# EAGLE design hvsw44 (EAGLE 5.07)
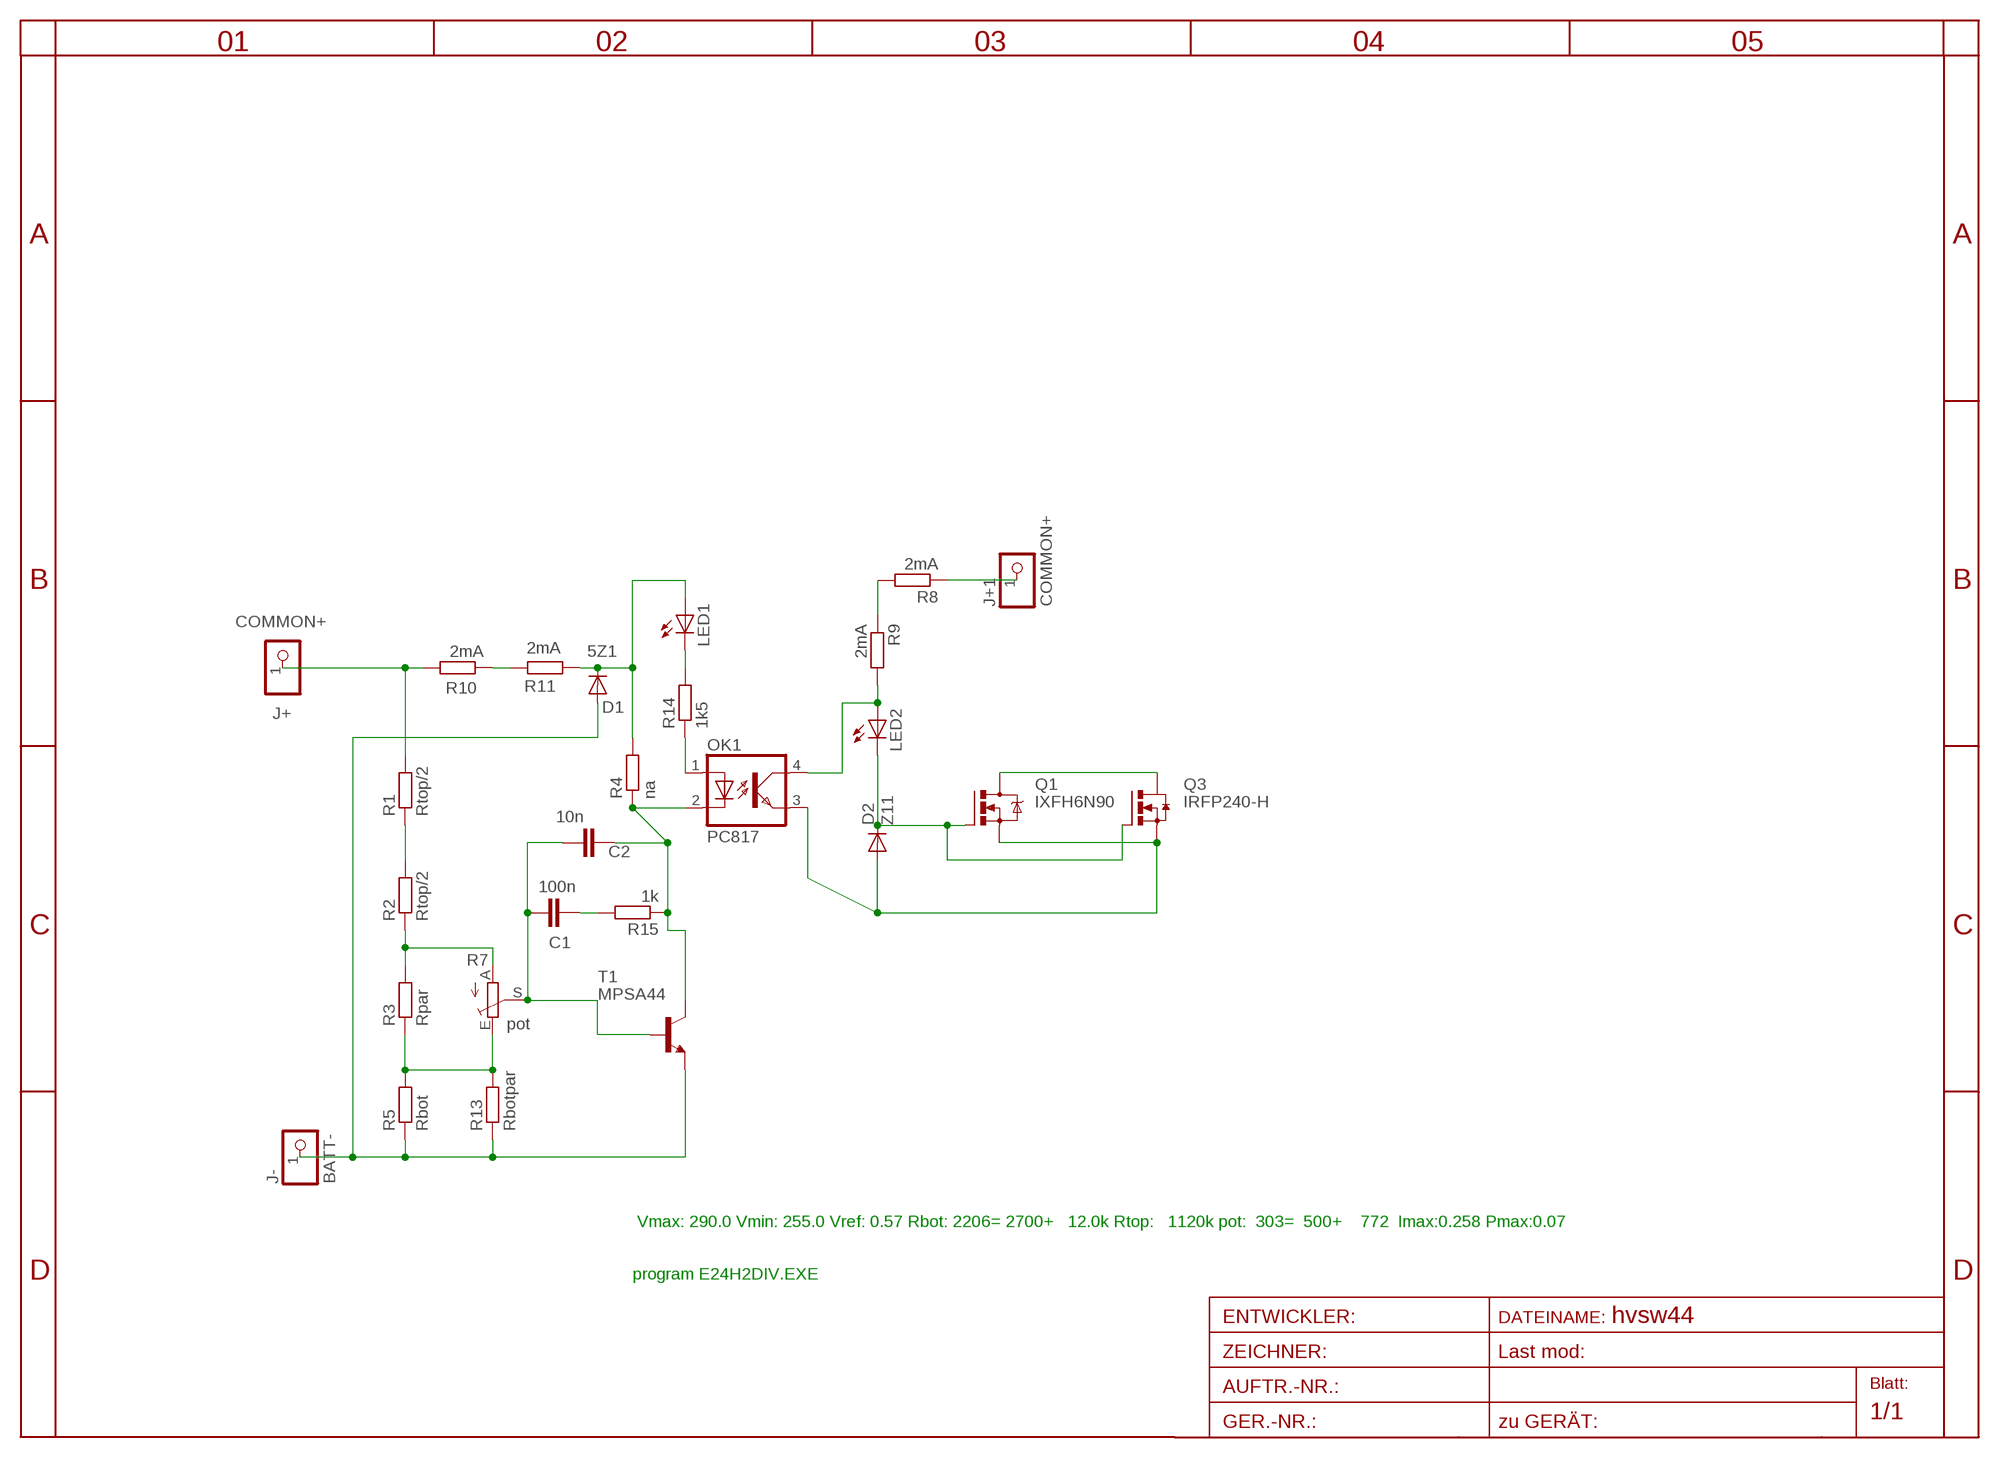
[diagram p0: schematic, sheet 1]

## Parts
C1  100n  C-EUC0805  [C0805]
C2  10n  C-EUC0805  [C0805]
D1  5Z1  DIODE-MINIMELF  [MINIMELF]
D2  Z11  DIODE-MINIMELF  [MINIMELF]
J+  COMMON+  PINHD-1X11X0.4  [1X01]
J+1  COMMON+  PINHD-1X11X0.4  [1X01]
J-  BATT-  PINHD-1X11X0.4  [1X01]
LED1  LED3MM  [LED3MM]
LED2  LED3MM  [LED3MM]
OK1  PC817  [DIL04]
Q1  IXFH6N90  [TO-247AD-V]
Q3  IRFP240-H  [TO247BH]
R1  Rtop/2  R-EU_R1206  [R1206]
R2  Rtop/2  R-EU_R1206  [R1206]
R3  Rpar  R-EU_R1206  [R1206]
R4  na  R-EU_R0805  [R0805]
R5  Rbot  R-EU_R0805  [R0805]
R7  pot  TRIM_EU-CA6V  [CA6V]
R8  2mA  R-EU_R1206  [R1206]
R9  2mA  R-EU_R1206  [R1206]
R10  2mA  R-EU_R1206  [R1206]
R11  2mA  R-EU_R1206  [R1206]
R13  Rbotpar  R-EU_R0805  [R0805]
R14  1k5  R-EU_R0805  [R0805]
R15  1k  R-EU_R0805  [R0805]
T1  MPSA44  BC338-40-NPN-TO92-EBC  [TO92-EBC]

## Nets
A: R2.1 R3.2 R7.A
BATT-: D1.A J-.1 R5.1 R13.1 T1.E
D: Q1.D Q3.D
E: R3.1 R5.2 R7.E R13.2
G: D2.C LED2.K(C) Q1.G Q3.G
N$2: C1.2 C2.2 R7.S T1.B
N$3: C1.1 R15.2
N$5: J+.1 R1.2 R10.2
N$6: J+1.1 R8.1
N$7: OK1.1(A) R14.1
N$8: LED2.A OK1.4(COL) R9.2
N$10: LED1.K(C) R14.2
N$12: R8.2 R9.1
N$15: R1.1 R2.2
N$16: R10.1 R11.2
OK2: C2.1 OK1.2(C) R4.1 R15.1 T1.C
S: D2.A OK1.3(EMIT) Q1.S Q3.S
V_R: D1.C LED1.A R4.2 R11.1

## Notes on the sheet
- Vmax: 290.0 Vmin: 255.0 Vref: 0.57 Rbot: 2206= 2700+   12.0k Rtop:   1120k pot:  303=  500+    772  Imax:0.258 Pmax:0.07
- program E24H2DIV.EXE

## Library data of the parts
C1 C2 = rcl:C-EU: CAPACITOR, European symbol
D1 D2 = diode:DIODE-: DIODE
J+ J+1 J- = pinhead:PINHD-1X1: PIN HEADER
LED1 LED2 = led:LED: LED
OK1 = optocoupler:PC817: SHARP OPTO COUPLER
Q1 = transistor-power:IXF?6N*: HiPerFET (TM) Power MOSFET N-Channel Enhancement Mode HDMOS Family Source: http://www.ixys.com/91529.pdf
Q3 = transistor-power:IRFP240: HEXFET Power MosFet Source: http://www.irf.com/
R1-R5 R8-R11 R13-R15 = rcl:R-EU_: RESISTOR, European symbol
R7 = pot:TRIM_EU-: POTENTIOMETER
T1 = transistor:*-NPN-: NPN Transistror BF959 corrected 2008.03.06

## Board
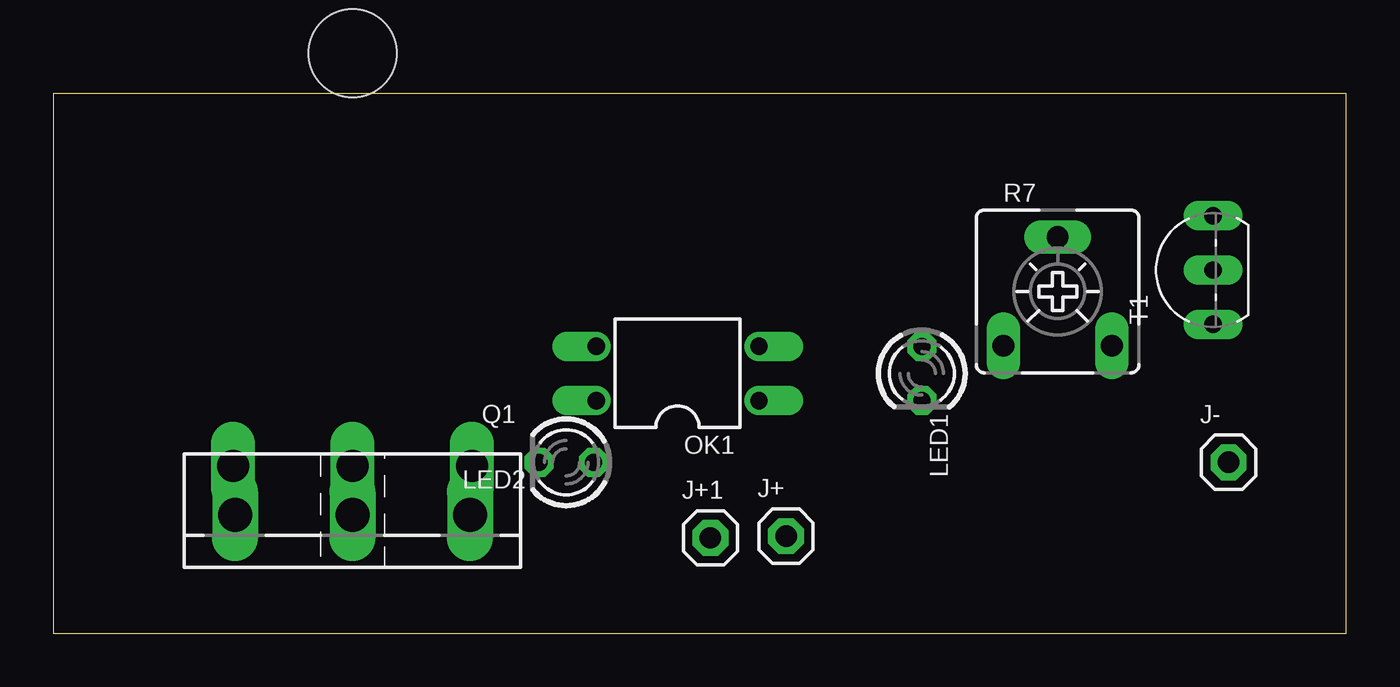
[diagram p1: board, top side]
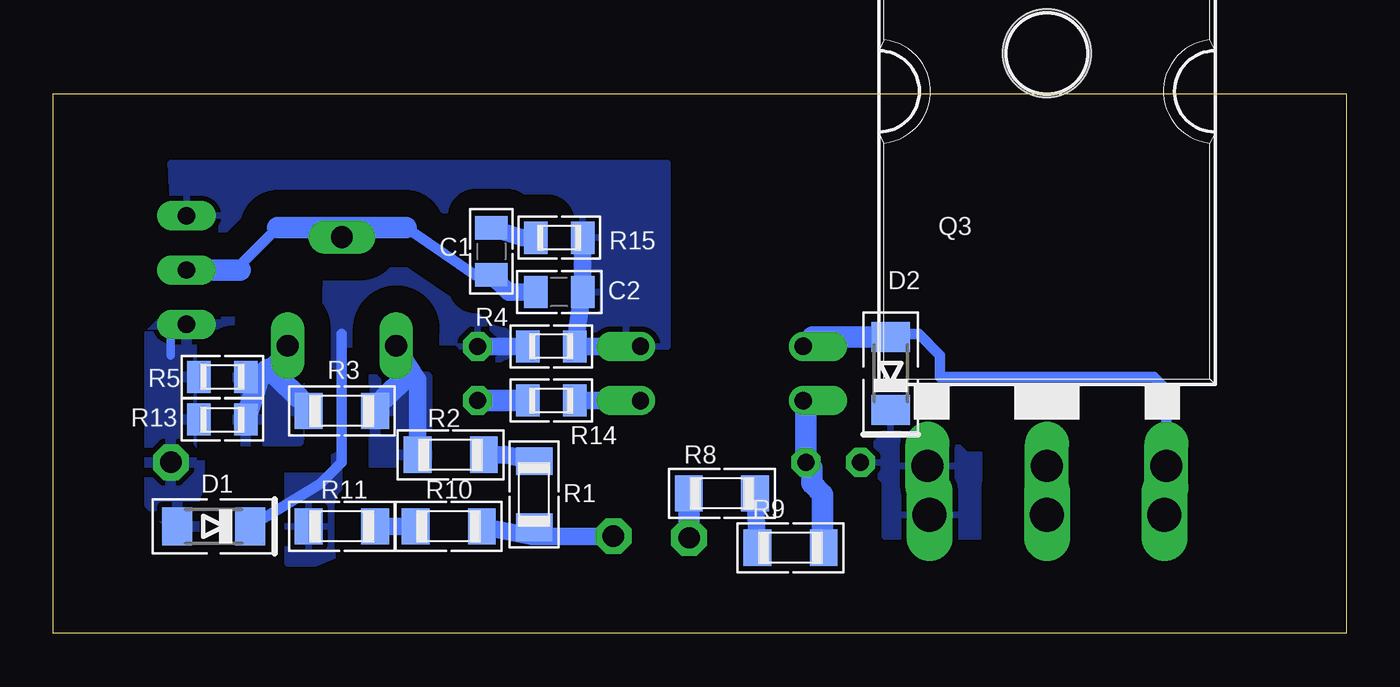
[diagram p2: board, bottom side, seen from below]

Size 60.5 x 25.26 mm. Coordinates in mm from the lower left corner, seen from the top.
Outline: 0,0 60.5,0 60.5,25.26 0,25.26 0,0
Copper layers (1*16): Top 0.035mm / dielectric 1.5mm / Bottom 0.035mm
Design rules "default *": minimum track width 10mil, minimum drill 20mil, track to track 8mil, track to pad 8mil, pad to pad 8mil, via to via 8mil, smd to smd 8mil, copper to edge 3mm, drill to drill 8mil, minimum pad ring 11mil, minimum via ring 8mil, stop-mask expansion 4mil, vias tented up to drill 0mil, thermal gap 10mil

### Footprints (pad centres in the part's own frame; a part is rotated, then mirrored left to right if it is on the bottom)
C0805 = smd 1.1 x 1.5: 1 -1.1,0; 2 1.1,0
MINIMELF = smd 1.4 x 1.8: A 1.7,0; C -1.7,0
1X01 = drill 1 pad 1.676 octagon: 1 0,0
LED3MM = drill 0.8 pad 1.27 octagon: A -1.27,0; K 1.27,0
DIL04 = drill 0.813 offset: 1 -1.27,-3.81; 2 1.27,-3.81; 3 1.27,3.81; 4 -1.27,3.81
TO-247AD-V = drill 1.6 long: D 0,-2.54; G -5.5,-2.54; S 5.5,-2.54
TO247BH = drill 1.499 long: D 0,-10.16; G -5.588,-10.16; S 5.588,-10.16 | hole 4.115: 0,9.144
R1206 = smd 1.3 x 1.7: 1 -1.55,0; 2 1.55,0
R0805 = smd 1.1 x 1.5: 1 -1.1,0; 2 1.1,0
CA6V = drill 1.016 long: A -2.54,-2.54; E 2.54,-2.54; S 0,2.54
TO92-EBC = drill 0.813 long: B 0,-1.27; C 2.54,-1.27; E -2.54,-1.27

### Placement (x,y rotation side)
C1  40.01,17.88 270 bottom
C2  36.83,15.97 180 bottom
D1  53,5 180 bottom
D2  21.32,12.16 90 bottom
J+  34.29,4.54 0 top
J+1  30.75,4.46 0 top
J-  55,8 0 top
LED1  40.64,12.16 270 top
LED2  24,8 180 top
OK1  29.21,12.16 90 top
Q1  14,3 180 top
Q3  14,18 0 bottom
R1  38,6.5 270 bottom
R2  41.91,8.35 0 bottom
R3  47,10.4 0 bottom
R4  37.2,13.43 180 bottom
R5  52.6,12 0 bottom
R7  47,16 0 top
R8  29.21,6.54 0 bottom
R9  26,4 0 bottom
R10  42,5 0 bottom
R11  47,5 0 bottom
R13  52.6,10 0 bottom
R14  37.2,10.89 180 bottom
R15  36.83,18.51 180 bottom
T1  53,17 90 top

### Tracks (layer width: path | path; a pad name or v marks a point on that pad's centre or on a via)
A
  Bottom 0.5: 45,11 R3.2 | 44,12 44,13 R7.A
  Bottom 0.813: R2.1 43.46,11.88 R7.A
  Bottom 1: 44,12 45,11
  pour Bottom (isolate 1): 43,12 46,12 46,8 43,8
BATT-
  Bottom 0.406: T1.E 55,14.46 55,13
  pour Bottom (isolate 1.676, rank 3): 52,15 55,15 56,14 56,6 54,4 51,4 51,14
D
  Bottom 0.5: Q1.D Q3.D
E
  Bottom 0.5: 49,11 R3.1 | 50,12 50,13 R7.E
  Bottom 0.813: R5.2 50.47,12.35 49.36,13.26 R7.E
  Bottom 1: 50,12 49,11 | R13.2 50.9,11.92 50.47,12.35
  pour Bottom (isolate 1): 49,12 52,12 52,9 49,9
G
  Bottom 0.813: D2.C 21.16,10.46
  pour Bottom (isolate 2): 16.43,8.35 17.78,8.35 20.32,10.89 25.4,10.89 25.4,9.62 24.13,9.62 21.59,7.08 21.59,4.54 16.43,4.54
N$2
  Bottom 0.406: 51.76,17.24 51.76,17
  Bottom 0.5: C1.2 40.77,16.77 44,19 | 50,19 51.76,17.24 | 47.46,19 R7.S
  Bottom 0.813: C2.2 39.2,15.97 C1.2
  Bottom 1: 44,19 47.46,19 50,19 | 51.76,17 T1.B
N$3
  Bottom 0.813: R15.2 38.56,18.51 C1.1
N$5
  Bottom 0.813: J+.1 38.1,4.54 | 38.1,4.54 R10.2 | 38.1,4.54 R1.2
N$6
  Bottom 1: J+1.1 R8.1
N$7
  Bottom 0.813: OK1.1 R14.1
N$8
  Bottom 1: R9.2 24.5,4 24.5,6.5 25,7 25,7.73 LED2.A 25.27,10.76 OK1.4
N$10
  Bottom 1: R14.2 LED1.K
N$12
  Bottom 0.813: R9.1 R8.2
N$15
  Bottom 0.813: R1.1 39.38,8.36 39.37,8.35 R2.2
N$16
  Bottom 0.813: R10.1 R11.2
OK2
  Bottom 0.813: OK1.2 R4.1 C2.1 R15.1
  pour Bottom (isolate 1.27): 31.75,13.43 31.75,22 55,22 54.8,18.51 36.83,18.51 36.83,13.43
S
  Bottom 0.5: Q3.S 8.41,11.41 9,12 19,12 19,13 20,14 21.46,14 | 21.46,14 22,14 | 21.46,14 D2.A | 24.97,13.86 OK1.3
  Bottom 1: D2.A 24.97,13.86 | Q1.S 8.5,7.75 Q3.S
V_R
  Bottom 0.5: D1.C 48.02,6.99 47,8 47,14
  Bottom 0.813: R4.2 LED1.A
  pour Bottom (isolate 1.25, rank 2): 38.1,14.7 39.37,16.97 47.72,16.97 47.99,10.89 49.53,8.35 49.53,3.27 48.26,3.27 46.26,4.08 44.72,6.62 44.45,12.16 41.91,12.16 40.64,10.89 38.1,10.89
